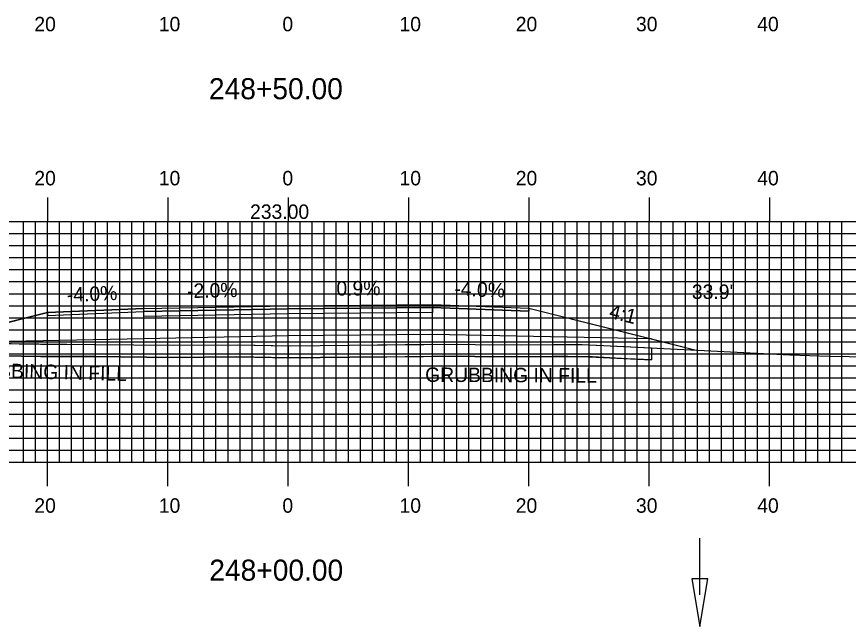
# Model space of a CAD drawing. Extents: x 1803503 to 1803847, y 442591 to 442811.
# Drawn here: x 1803646.6 to 1803715.7, y 442635 to 442685.7 of the extents above; entities that cross this region are included whole.
import ezdxf

# ---------------------------------------------------------------- set-up
doc = ezdxf.new("R2010")
doc.units = 0
for name, color, linetype in [('ANNOTATION', 7, 'Continuous'), ('D_Drainage_Ditch_Line', 7, 'Continuous'), ('D_Roadway_Centerline', 7, 'Continuous'), ('D_Roadway_Centerline_Text', 7, 'Continuous'), ('D_Roadway_Edge_Shoulder', 7, 'Continuous'), ('D_Roadway_Edge_TW', 7, 'Continuous'), ('D_Roadway_Pavement', 7, 'Continuous'), ('D_Roadway_SlopeLines', 7, 'Continuous'), ('D_Roadway_SubGrade', 7, 'Continuous'), ('D_Text_Standard', 7, 'Continuous'), ('GRUBBING IN FILL', 7, 'Continuous'), ('H_V ANNOTATION', 7, 'Continuous'), ('MAJOR', 7, 'Continuous'), ('MINOR', 7, 'Continuous'), ('S_Roadway_Centerline', 7, 'Continuous')]:
    doc.layers.add(name, color=color, linetype=linetype)

msp = doc.modelspace()

# ---------------------------------------------------------------- linework, layer by layer
at = {"layer": 'D_Drainage_Ditch_Line'}
msp.add_line((1803703.343, 442637.65), (1803703.343, 442642.349), dxfattribs=at)
msp.add_lwpolyline([(1803703.999, 442638.962), (1803702.687, 442638.962), (1803703.343, 442635.025)], close=True, dxfattribs=at)
at = {"layer": 'D_Roadway_Centerline'}
msp.add_lwpolyline([(1803627.728, 442658.786), (1803628.978, 442658.731), (1803630.228, 442658.602), (1803631.478, 442658.4), (1803632.728, 442658.124), (1803634.967, 442657.564), (1803638.967, 442658.564), (1803649.141, 442661.108), (1803657.141, 442661.428), (1803669.141, 442661.668), (1803681.141, 442661.775), (1803689.141, 442661.455), (1803699.315, 442658.912), (1803703.03, 442657.983)], dxfattribs=at)
at = {"layer": 'D_Roadway_Edge_Shoulder'}
for points in [[(1803681.141, 442661.775), (1803689.141, 442661.455), (1803689.141, 442661.205), (1803681.141, 442661.525)], [(1803657.141, 442661.428), (1803649.141, 442661.108), (1803649.141, 442660.858), (1803657.141, 442661.178)]]:
    msp.add_lwpolyline(points, close=True, dxfattribs=at)
at = {"layer": 'D_Roadway_Edge_TW'}
msp.add_lwpolyline([(1803657.141, 442661.178), (1803657.141, 442661.428), (1803669.141, 442661.668), (1803681.141, 442661.775), (1803681.141, 442661.525), (1803669.141, 442661.418)], close=True, dxfattribs=at)
at = {"layer": 'D_Roadway_Pavement'}
msp.add_lwpolyline([(1803657.141, 442660.761), (1803657.141, 442661.178), (1803669.141, 442661.418), (1803681.141, 442661.525), (1803681.141, 442661.109), (1803669.141, 442661.001)], close=True, dxfattribs=at)
at = {"layer": 'D_Roadway_SlopeLines'}
for points in [[(1803649.141, 442661.108), (1803634.967, 442657.564)], [(1803689.141, 442661.455), (1803703.03, 442657.983)]]:
    msp.add_lwpolyline(points, dxfattribs=at)
at = {"layer": 'D_Roadway_SubGrade'}
msp.add_lwpolyline([(1803657.141, 442658.928), (1803638.967, 442658.564), (1803649.141, 442661.108), (1803649.141, 442660.858), (1803657.141, 442661.178), (1803669.141, 442661.418), (1803681.141, 442661.525), (1803689.141, 442661.205), (1803689.141, 442661.455), (1803699.315, 442658.912), (1803681.141, 442659.275), (1803669.141, 442659.168)], close=True, dxfattribs=at)
at = {"layer": 'GRUBBING IN FILL'}
msp.add_line((1803699.315, 442658.167), (1803699.315, 442657.165), dxfattribs=at)
msp.add_line((1803699.315, 442658.167), (1803699.315, 442657.165), dxfattribs=at)
for points in [[(1803638.967, 442657.613), (1803638.967, 442658.564), (1803640.322, 442658.591), (1803641.483, 442658.573), (1803653.042, 442658.437), (1803659.575, 442658.377), (1803664.893, 442658.416), (1803669.141, 442658.327), (1803669.141, 442657.326), (1803664.886, 442657.416), (1803659.574, 442657.377), (1803653.035, 442657.437), (1803648.563, 442657.458), (1803643.765, 442657.536)], [(1803638.967, 442657.613), (1803638.967, 442658.564), (1803640.322, 442658.591), (1803641.483, 442658.573), (1803653.042, 442658.437), (1803659.575, 442658.377), (1803664.893, 442658.416), (1803669.141, 442658.327), (1803669.141, 442657.326), (1803664.886, 442657.416), (1803659.574, 442657.377), (1803653.035, 442657.437), (1803648.563, 442657.458), (1803643.765, 442657.536)], [(1803669.141, 442657.326), (1803669.141, 442658.327), (1803671.801, 442658.356), (1803674.246, 442658.391), (1803678.863, 442658.432), (1803683.48, 442658.473), (1803684.671, 442658.439), (1803688.533, 442658.421), (1803691.206, 442658.435), (1803693.521, 442658.442), (1803695.327, 442658.364), (1803699.315, 442658.167), (1803699.315, 442657.165), (1803697.297, 442657.265), (1803694.436, 442657.405), (1803692.386, 442657.439), (1803691.21, 442657.435), (1803688.53, 442657.421), (1803684.66, 442657.439), (1803683.471, 442657.472), (1803678.864, 442657.432), (1803674.258, 442657.391), (1803669.352, 442657.322)], [(1803669.141, 442657.326), (1803669.141, 442658.327), (1803671.801, 442658.356), (1803674.246, 442658.391), (1803678.863, 442658.432), (1803683.48, 442658.473), (1803684.671, 442658.439), (1803688.533, 442658.421), (1803691.206, 442658.435), (1803693.521, 442658.442), (1803695.327, 442658.364), (1803699.315, 442658.167), (1803699.315, 442657.165), (1803697.297, 442657.265), (1803694.436, 442657.405), (1803692.386, 442657.439), (1803691.21, 442657.435), (1803688.53, 442657.421), (1803684.66, 442657.439), (1803683.471, 442657.472), (1803678.864, 442657.432), (1803674.258, 442657.391), (1803669.352, 442657.322)]]:
    msp.add_lwpolyline(points, close=True, dxfattribs=at)
msp.add_lwpolyline([(1803638.967, 442657.613), (1803648.563, 442657.458), (1803653.035, 442657.437), (1803659.574, 442657.377), (1803664.886, 442657.416), (1803669.352, 442657.322), (1803674.258, 442657.391), (1803683.471, 442657.472), (1803685.85, 442657.406), (1803691.21, 442657.435), (1803693.562, 442657.442), (1803693.594, 442657.445), (1803695.278, 442657.365), (1803699.315, 442657.165)], dxfattribs=at)
msp.add_lwpolyline([(1803638.967, 442657.613), (1803648.563, 442657.458), (1803653.035, 442657.437), (1803659.574, 442657.377), (1803664.886, 442657.416), (1803669.352, 442657.322), (1803674.258, 442657.391), (1803683.471, 442657.472), (1803685.85, 442657.406), (1803691.21, 442657.435), (1803693.562, 442657.442), (1803693.594, 442657.445), (1803695.278, 442657.365), (1803699.315, 442657.165)], dxfattribs=at)
at = {"layer": 'MAJOR'}
for p, q in [((1803649.141, 442670.669), (1803649.141, 442668.665)), ((1803659.141, 442670.669), (1803659.141, 442668.665)), ((1803669.141, 442670.669), (1803669.141, 442668.665)), ((1803679.141, 442670.669), (1803679.141, 442668.665)), ((1803689.141, 442670.669), (1803689.141, 442668.665)), ((1803699.141, 442670.669), (1803699.141, 442668.665)), ((1803709.141, 442670.669), (1803709.141, 442668.665)), ((1803529.141, 442668.665), (1803809.141, 442668.665)), ((1803529.141, 442668.665), (1803809.141, 442668.665)), ((1803649.141, 442648.665), (1803649.141, 442668.665)), ((1803659.141, 442648.665), (1803659.141, 442668.665)), ((1803669.141, 442648.665), (1803669.141, 442668.665)), ((1803679.141, 442648.665), (1803679.141, 442668.665)), ((1803689.141, 442648.665), (1803689.141, 442668.665)), ((1803699.141, 442648.665), (1803699.141, 442668.665)), ((1803709.141, 442648.665), (1803709.141, 442668.665)), ((1803529.141, 442663.665), (1803809.141, 442663.665)), ((1803529.141, 442658.665), (1803809.141, 442658.665)), ((1803529.141, 442653.665), (1803809.141, 442653.665)), ((1803529.141, 442648.665), (1803809.141, 442648.665)), ((1803529.141, 442648.665), (1803809.141, 442648.665)), ((1803649.141, 442646.661), (1803649.141, 442648.665)), ((1803659.141, 442646.661), (1803659.141, 442648.665)), ((1803669.141, 442646.661), (1803669.141, 442648.665)), ((1803679.141, 442646.661), (1803679.141, 442648.665)), ((1803689.141, 442646.661), (1803689.141, 442648.665)), ((1803699.141, 442646.661), (1803699.141, 442648.665)), ((1803709.141, 442646.661), (1803709.141, 442648.665))]:
    msp.add_line(p, q, dxfattribs=at)
at = {"layer": 'MINOR'}
for p, q in [((1803647.141, 442648.665), (1803647.141, 442668.665)), ((1803648.141, 442648.665), (1803648.141, 442668.665)), ((1803650.141, 442648.665), (1803650.141, 442668.665)), ((1803651.141, 442648.665), (1803651.141, 442668.665)), ((1803652.141, 442648.665), (1803652.141, 442668.665)), ((1803653.141, 442648.665), (1803653.141, 442668.665)), ((1803654.141, 442648.665), (1803654.141, 442668.665)), ((1803655.141, 442648.665), (1803655.141, 442668.665)), ((1803656.141, 442648.665), (1803656.141, 442668.665)), ((1803657.141, 442648.665), (1803657.141, 442668.665)), ((1803658.141, 442648.665), (1803658.141, 442668.665)), ((1803660.141, 442648.665), (1803660.141, 442668.665)), ((1803661.141, 442648.665), (1803661.141, 442668.665)), ((1803662.141, 442648.665), (1803662.141, 442668.665)), ((1803663.141, 442648.665), (1803663.141, 442668.665)), ((1803664.141, 442648.665), (1803664.141, 442668.665)), ((1803665.141, 442648.665), (1803665.141, 442668.665)), ((1803666.141, 442648.665), (1803666.141, 442668.665)), ((1803667.141, 442648.665), (1803667.141, 442668.665)), ((1803668.141, 442648.665), (1803668.141, 442668.665)), ((1803670.141, 442648.665), (1803670.141, 442668.665)), ((1803671.141, 442648.665), (1803671.141, 442668.665)), ((1803672.141, 442648.665), (1803672.141, 442668.665)), ((1803673.141, 442648.665), (1803673.141, 442668.665)), ((1803674.141, 442648.665), (1803674.141, 442668.665)), ((1803675.141, 442648.665), (1803675.141, 442668.665)), ((1803676.141, 442648.665), (1803676.141, 442668.665)), ((1803677.141, 442648.665), (1803677.141, 442668.665)), ((1803678.141, 442648.665), (1803678.141, 442668.665)), ((1803680.141, 442648.665), (1803680.141, 442668.665)), ((1803681.141, 442648.665), (1803681.141, 442668.665)), ((1803682.141, 442648.665), (1803682.141, 442668.665)), ((1803683.141, 442648.665), (1803683.141, 442668.665)), ((1803684.141, 442648.665), (1803684.141, 442668.665)), ((1803685.141, 442648.665), (1803685.141, 442668.665)), ((1803686.141, 442648.665), (1803686.141, 442668.665)), ((1803687.141, 442648.665), (1803687.141, 442668.665)), ((1803688.141, 442648.665), (1803688.141, 442668.665)), ((1803690.141, 442648.665), (1803690.141, 442668.665)), ((1803691.141, 442648.665), (1803691.141, 442668.665)), ((1803692.141, 442648.665), (1803692.141, 442668.665)), ((1803693.141, 442648.665), (1803693.141, 442668.665)), ((1803694.141, 442648.665), (1803694.141, 442668.665)), ((1803695.141, 442648.665), (1803695.141, 442668.665)), ((1803696.141, 442648.665), (1803696.141, 442668.665)), ((1803697.141, 442648.665), (1803697.141, 442668.665)), ((1803698.141, 442648.665), (1803698.141, 442668.665)), ((1803700.141, 442648.665), (1803700.141, 442668.665)), ((1803701.141, 442648.665), (1803701.141, 442668.665)), ((1803702.141, 442648.665), (1803702.141, 442668.665)), ((1803703.141, 442648.665), (1803703.141, 442668.665)), ((1803704.141, 442648.665), (1803704.141, 442668.665)), ((1803705.141, 442648.665), (1803705.141, 442668.665)), ((1803706.141, 442648.665), (1803706.141, 442668.665)), ((1803707.141, 442648.665), (1803707.141, 442668.665)), ((1803708.141, 442648.665), (1803708.141, 442668.665)), ((1803710.141, 442648.665), (1803710.141, 442668.665)), ((1803711.141, 442648.665), (1803711.141, 442668.665)), ((1803712.141, 442648.665), (1803712.141, 442668.665)), ((1803713.141, 442648.665), (1803713.141, 442668.665)), ((1803714.141, 442648.665), (1803714.141, 442668.665)), ((1803715.141, 442648.665), (1803715.141, 442668.665)), ((1803529.141, 442667.665), (1803809.141, 442667.665)), ((1803529.141, 442666.665), (1803809.141, 442666.665)), ((1803529.141, 442665.665), (1803809.141, 442665.665)), ((1803529.141, 442664.665), (1803809.141, 442664.665)), ((1803529.141, 442662.665), (1803809.141, 442662.665)), ((1803529.141, 442661.665), (1803809.141, 442661.665)), ((1803529.141, 442660.665), (1803809.141, 442660.665)), ((1803529.141, 442659.665), (1803809.141, 442659.665)), ((1803529.141, 442657.665), (1803809.141, 442657.665)), ((1803529.141, 442656.665), (1803809.141, 442656.665)), ((1803529.141, 442655.665), (1803809.141, 442655.665)), ((1803529.141, 442654.665), (1803809.141, 442654.665)), ((1803529.141, 442652.665), (1803809.141, 442652.665)), ((1803529.141, 442651.665), (1803809.141, 442651.665)), ((1803529.141, 442650.665), (1803809.141, 442650.665)), ((1803529.141, 442649.665), (1803809.141, 442649.665))]:
    msp.add_line(p, q, dxfattribs=at)
at = {"layer": 'S_Roadway_Centerline'}
msp.add_lwpolyline([(1803609.949, 442659.029), (1803614.977, 442658.948), (1803627.512, 442658.789), (1803634.393, 442658.687), (1803648.573, 442658.458), (1803653.042, 442658.437), (1803659.575, 442658.377), (1803664.893, 442658.416), (1803669.356, 442658.322), (1803674.246, 442658.391), (1803683.48, 442658.473), (1803685.861, 442658.406), (1803691.206, 442658.435), (1803693.521, 442658.442), (1803693.577, 442658.447), (1803695.327, 442658.364), (1803704.268, 442657.922), (1803710.833, 442657.578), (1803714.077, 442657.484), (1803724.068, 442657.305)], dxfattribs=at)

# ---------------------------------------------------------------- texts
at = {"layer": 'ANNOTATION'}
for s, rotation, p in [('0.9%', 0.51452, (1803673.154, 442662.504)), ('-4.0%', 2.29061, (1803650.773, 442661.975)), ('-2.0%', 1.14576, (1803660.747, 442662.3)), ('-4.0%', 357.70939, (1803682.933, 442662.505)), ('4:1', 345.96376, (1803695.734, 442660.669))]:
    msp.add_text(s, height=1.2, rotation=rotation, dxfattribs=at).set_placement(p)
at = {"layer": 'D_Roadway_Centerline'}
for s, p in [('C', (1803669.136, 442661.668)), ('L', (1803669.141, 442661.66))]:
    msp.add_text(s, height=0.0146, dxfattribs=at).set_placement(p)
at = {"layer": 'D_Roadway_Centerline_Text'}
msp.add_text('233.00', height=1.2, dxfattribs=at).set_placement((1803665.973, 442668.879))
at = {"layer": 'D_Text_Standard'}
msp.add_text("33.9'", height=1.2, dxfattribs=at).set_placement((1803702.685, 442662.228))
at = {"layer": 'GRUBBING IN FILL'}
for rotation, p in [(358.55884, (1803641.468, 442655.77)), (359.72808, (1803680.519, 442655.341))]:
    msp.add_text('GRUBBING IN FILL', height=1.2, rotation=rotation, dxfattribs=at).set_placement(p)
at = {"layer": 'H_V ANNOTATION'}
for s, height, p in [('20', 1.2, (1803648.049, 442684.465)), ('10', 1.2, (1803658.392, 442684.465)), ('0', 1.2, (1803668.659, 442684.465)), ('10', 1.2, (1803678.392, 442684.465)), ('20', 1.2, (1803688.049, 442684.465)), ('30', 1.2, (1803698.038, 442684.465)), ('40', 1.2, (1803708.113, 442684.465)), ('248+50.00', 1.75, (1803662.555, 442678.821)), ('20', 1.2, (1803648.049, 442671.665)), ('10', 1.2, (1803658.392, 442671.665)), ('0', 1.2, (1803668.659, 442671.665)), ('10', 1.2, (1803678.392, 442671.665)), ('20', 1.2, (1803688.049, 442671.665)), ('30', 1.2, (1803698.038, 442671.665)), ('40', 1.2, (1803708.113, 442671.665)), ('20', 1.2, (1803648.049, 442644.465)), ('10', 1.2, (1803658.392, 442644.465)), ('0', 1.2, (1803668.659, 442644.465)), ('10', 1.2, (1803678.392, 442644.465)), ('20', 1.2, (1803688.049, 442644.465)), ('30', 1.2, (1803698.038, 442644.465)), ('40', 1.2, (1803708.113, 442644.465)), ('248+00.00', 1.75, (1803662.586, 442638.821))]:
    msp.add_text(s, height=height, dxfattribs=at).set_placement(p)

doc.saveas('drawing.dxf')
